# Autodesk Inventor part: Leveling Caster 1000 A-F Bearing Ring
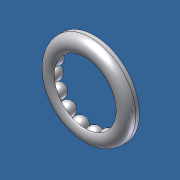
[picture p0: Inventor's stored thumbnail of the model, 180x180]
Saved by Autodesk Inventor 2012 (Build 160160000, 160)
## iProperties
Created: 2015-01
Part Number: Leveling Caster 1000 A-F Bearing Ring
Material: Default
Document SubType Name: Modeling
Designer: Admin
Density: 1 g/cm^3
Author: Admin
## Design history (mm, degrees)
feature "Base1"
body "Solid1"
